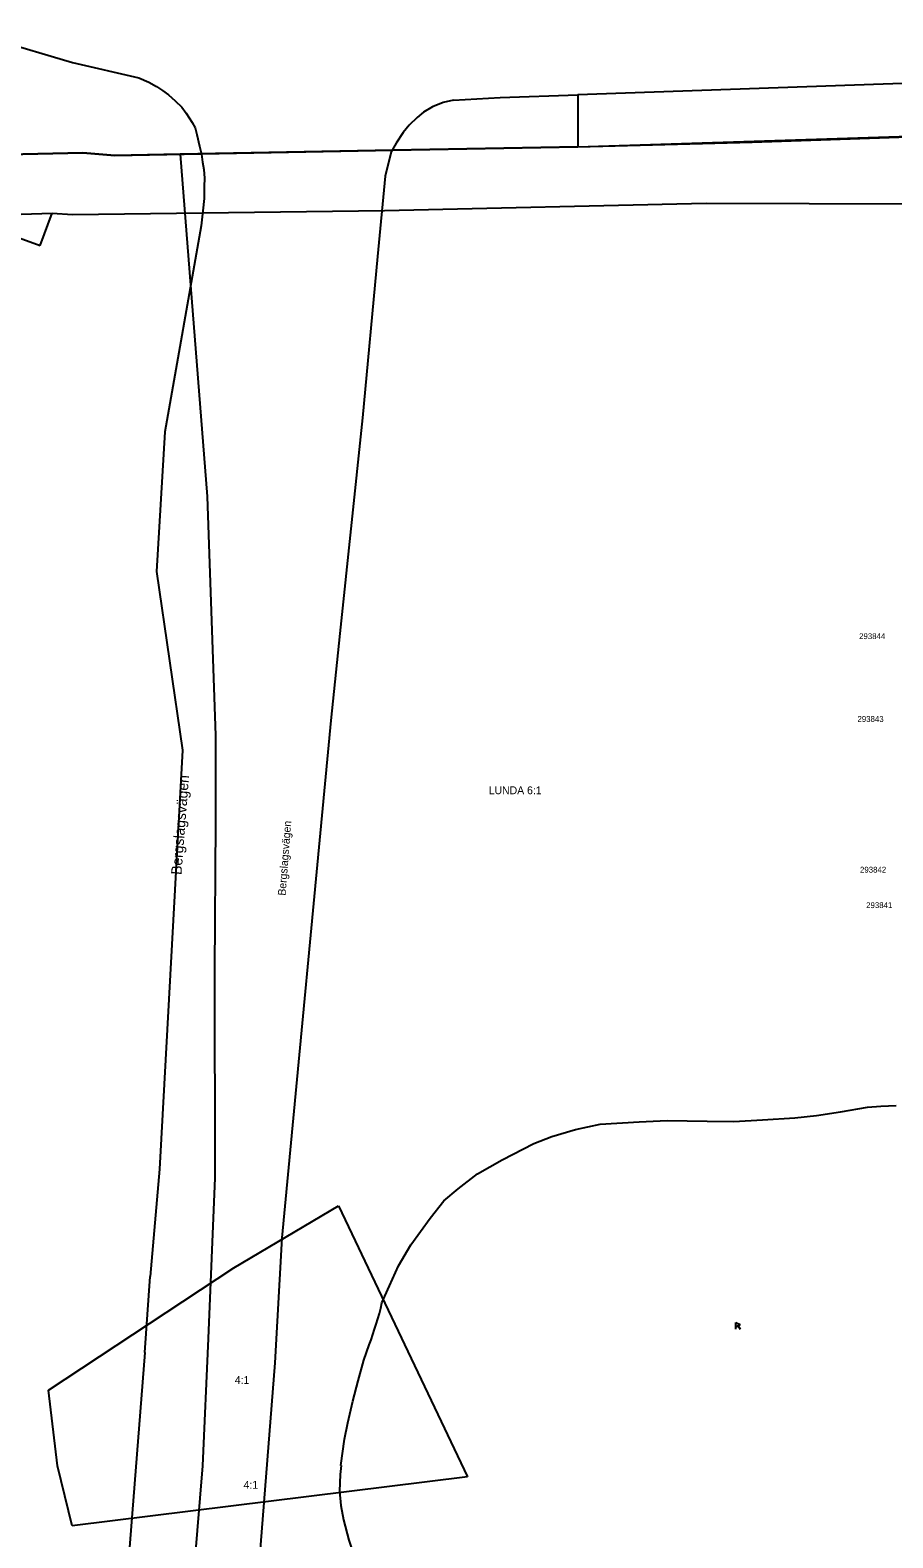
# Model space of a CAD drawing. Extents: x 141995 to 152570, y 6580184 to 6586000.
# Drawn here: x 142442.1 to 142574.5, y 6585633.6 to 6585865 of the extents above; entities that cross this region are included whole.
import ezdxf

# ---------------------------------------------------------------- set-up
doc = ezdxf.new("R2010")
doc.units = 0
for name, color, linetype in [('Level 12', 7, 'Continuous'), ('Level 13', 7, 'Continuous'), ('Level 20', 7, 'Continuous'), ('Level 21', 7, 'Continuous'), ('Level 40', 7, 'Continuous'), ('Level 43', 7, 'Continuous'), ('Level 5', 7, 'Continuous'), ('Level 51', 7, 'Continuous'), ('Level 53', 7, 'Continuous'), ('Level 59', 7, 'Continuous'), ('Level 6', 7, 'Continuous')]:
    doc.layers.add(name, color=color, linetype=linetype)

msp = doc.modelspace()

# ---------------------------------------------------------------- linework, layer by layer
at = {"layer": 'Level 12'}
for p, q in [((142550.39, 6585665.64), (142550.39, 6585666.64)), ((142550.39, 6585666.64), (142551.04, 6585666.34)), ((142551.04, 6585666.34), (142550.39, 6585665.94)), ((142550.72, 6585666.14), (142551.04, 6585665.64))]:
    msp.add_line(p, q, dxfattribs=at)
for points in [[(142545.98, 6585697.55), (142550.09, 6585697.51), (142554.46, 6585697.74), (142559.45, 6585698.06), (142562.78, 6585698.42), (142566.46, 6585699.01), (142570.57, 6585699.68), (142572.65, 6585699.87), (142575, 6585699.95)], [(142496.07, 6585669.68), (142497.21, 6585672.3), (142498.62, 6585675.32), (142500.52, 6585678.59), (142503.46, 6585682.65), (142505.59, 6585685.31), (142507.76, 6585687.19), (142510.73, 6585689.47), (142514.53, 6585691.6), (142519.39, 6585694.12), (142522.13, 6585695.18), (142525.78, 6585696.27), (142529.58, 6585697.08), (142535.53, 6585697.47), (142539.82, 6585697.64), (142545.97, 6585697.55)], [(142489.78, 6585644.68), (142490.32, 6585648.72), (142490.82, 6585651.27), (142491.59, 6585654.55), (142492.42, 6585657.7), (142493.32, 6585660.84), (142494.09, 6585663.22)], [(142489.83, 6585644.68), (142489.65, 6585643.3), (142489.58, 6585640.76), (142489.78, 6585638.57), (142490.17, 6585636.36), (142491.01, 6585633.22), (142491.85, 6585630.62), (142492.92, 6585628.34), (142494.53, 6585625.69), (142496.7, 6585622.64), (142498.54, 6585620.29), (142502.33, 6585615.39)]]:
    msp.add_lwpolyline(points, dxfattribs=at)
msp.add_arc((142454.03, 6585679.05), 43.08, 338.4331, 347.4312, dxfattribs=at)
at = {"layer": 'Level 13'}
for points in [[(142436.84, 6585863.56), (142448.58, 6585860.05)], [(142448.58, 6585860.05), (142458.78, 6585857.71)], [(142458.78, 6585857.71), (142460.31, 6585857.04), (142461.48, 6585856.36), (142462.42, 6585855.74), (142463.32, 6585855.08), (142464.34, 6585854.18), (142465.36, 6585853.22), (142466.03, 6585852.27), (142466.93, 6585850.84), (142467.4, 6585850.04), (142467.67, 6585849.01), (142468.09, 6585847.21), (142468.38, 6585846.01), (142468.55, 6585844.78), (142468.72, 6585843.63), (142468.86, 6585842.31), (142468.81, 6585841.01), (142468.8, 6585839.21), (142468.61, 6585837.31), (142468.33, 6585834.98), (142462.75, 6585803.36), (142461.5, 6585781.91), (142465.47, 6585754.49), (142461.95, 6585690.17), (142460.49, 6585673.7)], [(142507.07, 6585854.27), (142505.47, 6585853.92), (142503.82, 6585853.28), (142502.46, 6585852.46), (142501.46, 6585851.61), (142500.25, 6585850.42), (142499.35, 6585849.32), (142498.26, 6585847.68), (142497.48, 6585846.33), (142496.59, 6585842.61), (142495.41, 6585830.26), (142493.09, 6585805.52), (142489.63, 6585772.41), (142488.25, 6585759.04), (142480.7, 6585679.62)], [(142507.07, 6585854.27), (142514.22, 6585854.71), (142526.15, 6585855.09)], [(142480.7, 6585679.62), (142479.65, 6585660.46)], [(142459.71, 6585662.03), (142460.49, 6585673.7)], [(142459.71, 6585662.03), (142437.09, 6585375.26)], [(142479.65, 6585660.46), (142457.37, 6585377.83)]]:
    msp.add_lwpolyline(points, dxfattribs=at)
at = {"layer": 'Level 20'}
for points in [[(142450.19, 6585846.22), (142436.31, 6585845.91), (142416.82, 6585845.62), (142406.79, 6585845.47)], [(142465.11, 6585845.98), (142455.06, 6585845.78), (142450.19, 6585846.22)], [(142465.11, 6585845.98), (142469.25, 6585793.42), (142470.52, 6585756.76), (142470.52, 6585743.36), (142470.4, 6585720.85), (142470.43, 6585688.85), (142469.42, 6585664.2), (142468.56, 6585644.66)], [(142468.56, 6585644.66), (142445.03, 6585359.28), (142436.21, 6585244.62)]]:
    msp.add_lwpolyline(points, dxfattribs=at)
at = {"layer": 'Level 21'}
for points in [[(142526.16, 6585847.14), (142627.98, 6585850.39)], [(142450.19, 6585846.22), (142436.31, 6585845.91), (142416.82, 6585845.62), (142406.79, 6585845.47)], [(142465.11, 6585845.98), (142455.06, 6585845.78), (142450.19, 6585846.22)], [(142526.16, 6585847.14), (142497.73, 6585846.62), (142465.11, 6585845.98)], [(142465.11, 6585845.98), (142469.25, 6585793.42), (142470.52, 6585756.76), (142470.52, 6585743.36), (142470.4, 6585720.85), (142470.43, 6585688.85), (142469.42, 6585664.2), (142468.56, 6585644.66)], [(142468.56, 6585644.66), (142445.03, 6585359.28), (142436.21, 6585244.62)]]:
    msp.add_lwpolyline(points, dxfattribs=at)
at = {"layer": 'Level 5'}
for points in [[(142552.89, 6585847.83), (142627.98, 6585850.39)], [(142436.31, 6585845.91), (142450.19, 6585846.22)], [(142450.19, 6585846.22), (142455.06, 6585845.78)], [(142455.06, 6585845.78), (142497.73, 6585846.62)], [(142497.73, 6585846.62), (142526.16, 6585847.14)], [(142526.16, 6585847.14), (142552.89, 6585847.83)], [(142443.61, 6585831.98), (142445.48, 6585836.91)], [(142445.48, 6585836.91), (142448.57, 6585836.74)], [(142448.57, 6585836.74), (142496.48, 6585837.35)], [(142496.48, 6585837.35), (142545.85, 6585838.47)], [(142545.85, 6585838.47), (142577.43, 6585838.39)], [(142431.09, 6585836.5), (142443.61, 6585831.98)], [(142473.33, 6585675.05), (142489.42, 6585684.55)], [(142489.42, 6585684.55), (142509.21, 6585642.96)], [(142444.91, 6585656.27), (142473.33, 6585675.05)], [(142446.3, 6585644.64), (142444.91, 6585656.27)], [(142448.52, 6585635.44), (142446.3, 6585644.64)], [(142509.21, 6585642.96), (142448.52, 6585635.44)]]:
    msp.add_lwpolyline(points, dxfattribs=at)
at = {"layer": 'Level 6'}
for points in [[(143000, 6585862.54), (142951.18, 6585863.09), (142826.64, 6585863.23), (142810.19, 6585865.03), (142526.15, 6585855.09), (142526.16, 6585847.14), (142497.73, 6585846.62), (142455.06, 6585845.78), (142450.19, 6585846.22), (142436.31, 6585845.91), (142416.82, 6585845.62), (142406.79, 6585845.47), (142365.61, 6585844.86), (142354.53, 6585843.6), (142347.46, 6585843.44), (142347.66, 6585852.15), (142029.5, 6585846.1), (142000, 6585845.22)], [(142416.89, 6585836.01), (142445.48, 6585836.91), (142448.57, 6585836.74), (142496.48, 6585837.35), (142545.85, 6585838.47), (142577.43, 6585838.39), (142633.4, 6585837.48), (142638.53, 6585837.93), (142705.99, 6585836.9), (142770.54, 6585836.86), (142773.76, 6585836.98), (142785.14, 6585838.45), (142790.32, 6585840.63), (142794.8, 6585840.84), (142848.36, 6585837.76), (142869.99, 6585838.07), (142946.64, 6585840.47), (143000, 6585842.14)]]:
    msp.add_lwpolyline(points, dxfattribs=at)

# ---------------------------------------------------------------- texts
at = {"layer": 'Level 40'}
msp.add_text('Bergslagsvägen', height=1.2, rotation=85.5644, dxfattribs=at).set_placement((142481.28, 6585732.14))
at = {"layer": 'Level 43'}
msp.add_text('Bergslagsvägen', height=1.6, rotation=85.5644, dxfattribs=at).set_placement((142465.3, 6585735.32))
at = {"layer": 'Level 51'}
msp.add_text('LUNDA 6:1', height=1.2, dxfattribs=at).set_placement((142512.46, 6585747.74))
msp.add_text('4:1', height=1.2, rotation=0.0577, dxfattribs=at).set_placement((142473.49, 6585657.22))
at = {"layer": 'Level 53'}
for s, p in [('293844', (142569.3, 6585771.55)), ('293843', (142569.05, 6585758.84)), ('293842', (142569.44, 6585735.7)), ('293841', (142570.38, 6585730.26))]:
    msp.add_text(s, height=0.9, rotation=0.0451, dxfattribs=at).set_placement(p)
at = {"layer": 'Level 59'}
msp.add_text('4:1', height=1.2, rotation=0.0527, dxfattribs=at).set_placement((142474.84, 6585641.13))

doc.saveas('drawing.dxf')
